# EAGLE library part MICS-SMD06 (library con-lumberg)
CONNECTOR
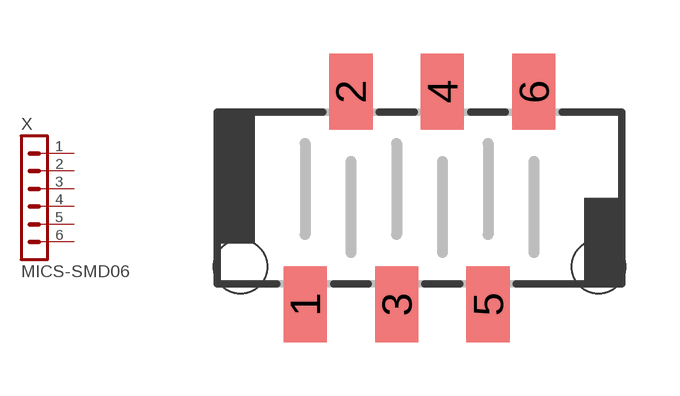
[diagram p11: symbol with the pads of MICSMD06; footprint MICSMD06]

Designator prefix X

## MICS-SMD06 (OC_FARNELL: unknown; OC_NEWARK: unknown)  [MICSMD06]
1  1  pas
2  2  pas
3  3  pas
4  4  pas
5  5  pas
6  6  pas

## Footprint MICSMD06 (pad centres in mm)
CONNECTOR
smd 1.2 x 2.1: 1 -3.175,-2.959; 2 -1.905,2.959; 3 -0.635,-2.959; 4 0.635,2.959; 5 1.905,-2.959; 6 3.175,2.959
hole 1.5 at 4.975,-1.912
hole 1.5 at -4.975,-1.912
